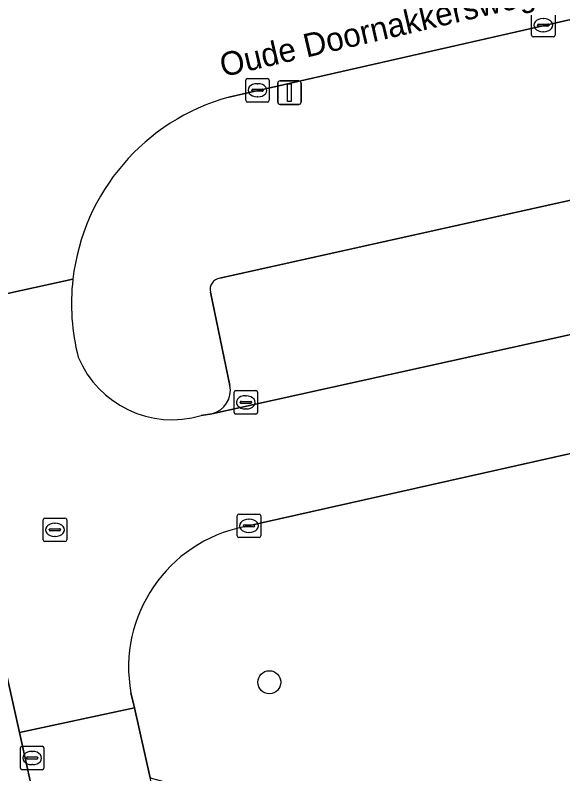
# Model space of a CAD drawing. Extents: x 164494 to 166241, y 382475 to 384495.
# Drawn here: x 164657.42 to 164680.68, y 383414.07 to 383446.31 of the extents above; entities that cross this region are included whole.
import ezdxf

# ---------------------------------------------------------------- set-up
doc = ezdxf.new("R2010")
doc.units = 0
for name, color, linetype in [('IMGEO_Boom', 7, 'Continuous'), ('IMGEO_Erf', 7, 'Continuous'), ('IMGEO_Groenvoorziening', 7, 'Continuous'), ('IMGEO_Kolk', 7, 'Continuous'), ('IMGEO_Lichtmast', 7, 'Continuous'), ('IMGEO_Openbare_ruimte_label', 7, 'Continuous'), ('IMGEO_Parkeervlak_open', 7, 'Continuous'), ('IMGEO_Rijbaan_lokaal_open', 7, 'Continuous'), ('IMGEO_Rioolput', 7, 'Continuous')]:
    doc.layers.add(name, color=color, linetype=linetype)

msp = doc.modelspace()

# ---------------------------------------------------------------- linework, layer by layer
at = {"layer": 'IMGEO_Boom'}
msp.add_circle((164668.213, 383417.967), 0.489, dxfattribs=at)
at = {"layer": 'IMGEO_Erf'}
msp.add_lwpolyline([(164662.088, 383395.82), (164659.432, 383407.619), (164658.436, 383412.043), (164658.352, 383412.424), (164657.598, 383415.827), (164656.836, 383419.271), (164654.781, 383428.342), (164653.876, 383432.334), (164653.262, 383433.646), (164653.108, 383433.931)], dxfattribs=at)
at = {"layer": 'IMGEO_Groenvoorziening'}
for points in [[(164696.172, 383449.592), (164666.487, 383442.83)], [(164666.11, 383435.14), (164701.141, 383442.934)], [(164666.536, 383430.582), (164665.713, 383434.537)], [(164704.167, 383432.878), (164667.135, 383424.569)], [(164665.311, 383429.296), (164665.766, 383429.371)], [(164662.331, 383417.513), (164662.477, 383416.873), (164663.156, 383413.902), (164668.435, 383412.478), (164668.243, 383411.624)]]:
    msp.add_lwpolyline(points, dxfattribs=at)
for centre, radius, start, end in [((164668.92, 383434.047), 9.114, 105.4856, 173.39), ((164668.91, 383434.044), 9.104, 173.3642, 194.4243), ((164666.182, 383434.66), 0.485, 98.564, 194.7162), ((164664.086, 383433.448), 4.329, 202.7182, 286.4403), ((164665.533, 383430.369), 1.025, 283.1335, 11.9669), ((164668.331, 383418.591), 6.097, 101.3178, 190.1851)]:
    msp.add_arc(centre, radius, start, end, dxfattribs=at)
at = {"layer": 'IMGEO_Kolk'}
for p, q in [((164679.349, 383445.461), (164679.349, 383446.313)), ((164680.35, 383446.313), (164680.35, 383445.461)), ((164679.651, 383445.93), (164680.049, 383445.93)), ((164679.837, 383446.167), (164679.862, 383446.167)), ((164679.608, 383445.881), (164679.608, 383445.893)), ((164680.046, 383445.844), (164679.648, 383445.844)), ((164679.86, 383445.607), (164679.835, 383445.607)), ((164680.092, 383445.893), (164680.092, 383445.881)), ((164680.276, 383445.387), (164679.424, 383445.387)), ((164667.207, 383442.695), (164667.207, 383443.547)), ((164667.282, 383443.621), (164668.134, 383443.621)), ((164667.695, 383443.401), (164667.72, 383443.401)), ((164668.208, 383443.547), (164668.208, 383442.695)), ((164667.466, 383443.115), (164667.466, 383443.127)), ((164667.904, 383443.078), (164667.506, 383443.078)), ((164667.509, 383443.164), (164667.907, 383443.164)), ((164667.95, 383443.127), (164667.95, 383443.115)), ((164667.718, 383442.841), (164667.693, 383442.841)), ((164668.134, 383442.621), (164667.282, 383442.621)), ((164666.711, 383429.434), (164666.711, 383430.286)), ((164666.786, 383430.36), (164667.638, 383430.36)), ((164667.199, 383430.14), (164667.224, 383430.14)), ((164667.712, 383430.286), (164667.712, 383429.434)), ((164666.97, 383429.854), (164666.97, 383429.866)), ((164667.408, 383429.817), (164667.01, 383429.817)), ((164667.013, 383429.903), (164667.411, 383429.903)), ((164667.454, 383429.866), (164667.454, 383429.854)), ((164667.222, 383429.58), (164667.197, 383429.58)), ((164667.638, 383429.36), (164666.786, 383429.36)), ((164666.848, 383424.186), (164666.848, 383425.038)), ((164666.923, 383425.112), (164667.775, 383425.112)), ((164667.849, 383425.038), (164667.849, 383424.186)), ((164667.107, 383424.606), (164667.107, 383424.618)), ((164667.15, 383424.655), (164667.548, 383424.655)), ((164667.336, 383424.892), (164667.361, 383424.892)), ((164667.591, 383424.618), (164667.591, 383424.606)), ((164667.545, 383424.569), (164667.147, 383424.569)), ((164667.359, 383424.332), (164667.334, 383424.332)), ((164667.775, 383424.112), (164666.923, 383424.112)), ((164657.637, 383414.32), (164657.637, 383415.172)), ((164657.712, 383415.246), (164658.564, 383415.246)), ((164658.125, 383415.026), (164658.15, 383415.026)), ((164658.638, 383415.172), (164658.638, 383414.32)), ((164657.896, 383414.74), (164657.896, 383414.752)), ((164658.334, 383414.703), (164657.936, 383414.703)), ((164657.939, 383414.789), (164658.337, 383414.789)), ((164658.38, 383414.752), (164658.38, 383414.74)), ((164658.148, 383414.466), (164658.123, 383414.466)), ((164658.564, 383414.246), (164657.712, 383414.246))]:
    msp.add_line(p, q, dxfattribs=at)
for points in [[(164679.349, 383445.461), (164679.349, 383446.313)], [(164680.35, 383446.313), (164680.35, 383445.461)], [(164680.276, 383445.387), (164679.424, 383445.387)], [(164667.207, 383442.695), (164667.207, 383443.547)], [(164667.282, 383443.621), (164668.134, 383443.621)], [(164668.208, 383443.547), (164668.208, 383442.695)], [(164668.134, 383442.621), (164667.282, 383442.621)], [(164666.711, 383429.434), (164666.711, 383430.286)], [(164666.786, 383430.36), (164667.638, 383430.36)], [(164667.712, 383430.286), (164667.712, 383429.434)], [(164667.638, 383429.36), (164666.786, 383429.36)], [(164666.848, 383424.186), (164666.848, 383425.038)], [(164666.923, 383425.112), (164667.775, 383425.112)], [(164667.849, 383425.038), (164667.849, 383424.186)], [(164667.775, 383424.112), (164666.923, 383424.112)], [(164657.637, 383414.32), (164657.637, 383415.172)], [(164657.712, 383415.246), (164658.564, 383415.246)], [(164658.638, 383415.172), (164658.638, 383414.32)], [(164658.564, 383414.246), (164657.712, 383414.246)]]:
    msp.add_lwpolyline(points, dxfattribs=at)
for centre, radius, start, end in [((164679.648, 383445.89), 0.0403, 85.8775, 175.7526), ((164680.053, 383445.892), 0.0386, 1.7309, 96.639), ((164679.645, 383445.88), 0.0366, 178.938, 274.7102), ((164680.049, 383445.887), 0.043, 264.8664, 352.4533), ((164679.426, 383445.463), 0.0765, 181.552, 268.448), ((164679.426, 383445.463), 0.0765, 181.552, 268.448), ((164680.274, 383445.463), 0.0765, 271.552, 358.448), ((164680.274, 383445.463), 0.0765, 271.552, 358.448), ((164667.284, 383443.545), 0.0765, 91.552, 178.448), ((164667.284, 383443.545), 0.0765, 91.552, 178.448), ((164668.132, 383443.545), 0.0765, 1.552, 88.448), ((164668.132, 383443.545), 0.0765, 1.552, 88.448), ((164667.506, 383443.124), 0.0403, 85.8775, 175.7526), ((164667.503, 383443.114), 0.0366, 178.938, 274.7102), ((164667.907, 383443.121), 0.043, 264.8664, 352.4533), ((164667.911, 383443.126), 0.0386, 1.7309, 96.639), ((164667.284, 383442.697), 0.0765, 181.552, 268.448), ((164667.284, 383442.697), 0.0765, 181.552, 268.448), ((164668.132, 383442.697), 0.0765, 271.552, 358.448), ((164668.132, 383442.697), 0.0765, 271.552, 358.448), ((164666.788, 383430.284), 0.0765, 91.552, 178.448), ((164666.788, 383430.284), 0.0765, 91.552, 178.448), ((164667.636, 383430.284), 0.0765, 1.552, 88.448), ((164667.636, 383430.284), 0.0765, 1.552, 88.448), ((164667.01, 383429.863), 0.0403, 85.8775, 175.7526), ((164667.007, 383429.853), 0.0366, 178.938, 274.7102), ((164667.411, 383429.86), 0.043, 264.8664, 352.4533), ((164667.415, 383429.865), 0.0386, 1.7309, 96.639), ((164666.788, 383429.436), 0.0765, 181.552, 268.448), ((164666.788, 383429.436), 0.0765, 181.552, 268.448), ((164667.636, 383429.436), 0.0765, 271.552, 358.448), ((164667.636, 383429.436), 0.0765, 271.552, 358.448), ((164666.925, 383425.036), 0.0765, 91.552, 178.448), ((164666.925, 383425.036), 0.0765, 91.552, 178.448), ((164667.773, 383425.036), 0.0765, 1.552, 88.448), ((164667.773, 383425.036), 0.0765, 1.552, 88.448), ((164667.147, 383424.615), 0.0403, 85.8775, 175.7526), ((164667.552, 383424.617), 0.0386, 1.7309, 96.639), ((164667.144, 383424.605), 0.0366, 178.938, 274.7102), ((164667.548, 383424.612), 0.043, 264.8664, 352.4533), ((164666.925, 383424.188), 0.0765, 181.552, 268.448), ((164666.925, 383424.188), 0.0765, 181.552, 268.448), ((164667.773, 383424.188), 0.0765, 271.552, 358.448), ((164667.773, 383424.188), 0.0765, 271.552, 358.448), ((164657.714, 383415.17), 0.0765, 91.552, 178.448), ((164657.714, 383415.17), 0.0765, 91.552, 178.448), ((164658.562, 383415.17), 0.0765, 1.552, 88.448), ((164658.562, 383415.17), 0.0765, 1.552, 88.448), ((164657.936, 383414.749), 0.0403, 85.8775, 175.7526), ((164657.933, 383414.739), 0.0366, 178.938, 274.7102), ((164658.337, 383414.746), 0.043, 264.8664, 352.4533), ((164658.341, 383414.751), 0.0386, 1.7309, 96.639), ((164657.714, 383414.322), 0.0765, 181.552, 268.448), ((164657.714, 383414.322), 0.0765, 181.552, 268.448), ((164658.562, 383414.322), 0.0765, 271.552, 358.448), ((164658.562, 383414.322), 0.0765, 271.552, 358.448)]:
    msp.add_arc(centre, radius, start, end, dxfattribs=at)
for centre, major_axis, ratio, start_param, end_param in [((164679.836, 383445.887), (-0.387, 0.002), 0.722429, 4.712389, 7.853982), ((164679.861, 383445.887), (-0.39, 0.002), 0.717154, 1.570796, 4.712389), ((164667.694, 383443.121), (-0.387, 0.002), 0.722429, 4.712389, 7.853982), ((164667.719, 383443.121), (-0.39, 0.002), 0.717154, 1.570796, 4.712389), ((164667.198, 383429.86), (-0.387, 0.002), 0.722429, 4.712389, 7.853982), ((164667.223, 383429.86), (-0.39, 0.002), 0.717154, 1.570796, 4.712389), ((164667.335, 383424.612), (-0.387, 0.002), 0.722429, 4.712389, 7.853982), ((164667.36, 383424.612), (-0.39, 0.002), 0.717154, 1.570796, 4.712389), ((164658.124, 383414.746), (-0.387, 0.002), 0.722429, 4.712389, 7.853982), ((164658.149, 383414.746), (-0.39, 0.002), 0.717154, 1.570796, 4.712389)]:
    msp.add_ellipse(centre, major_axis=major_axis, ratio=ratio, start_param=start_param, end_param=end_param, dxfattribs=at)
at = {"layer": 'IMGEO_Lichtmast'}
for p, q in [((164668.568, 383442.621), (164668.568, 383443.421)), ((164668.568, 383443.421), (164668.568, 383442.621)), ((164668.668, 383443.521), (164669.458, 383443.521)), ((164669.458, 383443.521), (164668.668, 383443.521)), ((164669.558, 383443.421), (164669.558, 383442.621)), ((164669.558, 383442.621), (164669.558, 383443.421)), ((164669.458, 383442.521), (164668.668, 383442.521)), ((164668.668, 383442.521), (164669.458, 383442.521))]:
    msp.add_line(p, q, dxfattribs=at)
msp.add_lwpolyline([(164668.988, 383443.396), (164669.138, 383443.396), (164669.138, 383442.646), (164668.988, 383442.646), (164668.988, 383443.396)], dxfattribs=at)
for centre, start, end in [((164668.668, 383443.421), 90, 180), ((164668.668, 383443.421), 90, 180), ((164669.458, 383443.421), 0, 90), ((164669.458, 383443.421), 360, 90), ((164668.668, 383442.621), 180, 270), ((164668.668, 383442.621), 180, 270), ((164669.458, 383442.621), 270, 0), ((164669.458, 383442.621), 270, 0)]:
    msp.add_arc(centre, 0.1, start, end, dxfattribs=at)
at = {"layer": 'IMGEO_Parkeervlak_open'}
for points in [[(164701.141, 383442.934), (164666.11, 383435.14)], [(164665.766, 383429.371), (164703.825, 383437.779)], [(164665.713, 383434.537), (164666.536, 383430.582)]]:
    msp.add_lwpolyline(points, dxfattribs=at)
for centre, radius, start, end in [((164666.182, 383434.66), 0.485, 98.564, 194.7162), ((164665.533, 383430.369), 1.025, 283.1335, 11.9669)]:
    msp.add_arc(centre, radius, start, end, dxfattribs=at)
at = {"layer": 'IMGEO_Rijbaan_lokaal_open'}
for points in [[(164666.487, 383442.83), (164696.172, 383449.592), (164718.625, 383455.027), (164719.856, 383455.391), (164720.68, 383455.635), (164719.895, 383459.238), (164717.739, 383458.983), (164712.427, 383457.585), (164708.916, 383456.753), (164693.004, 383452.936), (164678.342, 383449.582), (164665.421, 383446.666)], [(164650.16, 383445.637), (164653.262, 383433.646), (164659.867, 383435.096)], [(164703.825, 383437.779), (164665.766, 383429.371), (164665.311, 383429.296)], [(164659.867, 383435.096), (164653.262, 383433.646), (164653.876, 383432.334), (164654.781, 383428.342), (164656.836, 383419.271), (164657.598, 383415.827), (164662.477, 383416.873), (164662.331, 383417.513)], [(164667.135, 383424.569), (164704.167, 383432.878)]]:
    msp.add_lwpolyline(points, dxfattribs=at)
msp.add_lwpolyline([(164662.477, 383416.873), (164657.598, 383415.827), (164658.352, 383412.424), (164663.23, 383413.568), (164663.156, 383413.902)], close=True, dxfattribs=at)
for centre, radius, start, end in [((164668.92, 383434.047), 9.114, 105.4856, 173.39), ((164668.91, 383434.044), 9.104, 173.3642, 194.4243), ((164664.086, 383433.448), 4.329, 202.7182, 286.4403), ((164668.331, 383418.591), 6.097, 101.3178, 190.1851)]:
    msp.add_arc(centre, radius, start, end, dxfattribs=at)
at = {"layer": 'IMGEO_Rioolput'}
for p, q in [((164658.679, 383424.944), (164659.531, 383424.944)), ((164658.604, 383424.018), (164658.604, 383424.87)), ((164659.092, 383424.724), (164659.117, 383424.724)), ((164659.605, 383424.87), (164659.605, 383424.018)), ((164658.863, 383424.438), (164658.863, 383424.45)), ((164659.301, 383424.401), (164658.903, 383424.401)), ((164658.906, 383424.487), (164659.304, 383424.487)), ((164659.347, 383424.45), (164659.347, 383424.438)), ((164659.115, 383424.164), (164659.09, 383424.164)), ((164659.531, 383423.944), (164658.679, 383423.944))]:
    msp.add_line(p, q, dxfattribs=at)
for points in [[(164658.679, 383424.944), (164659.531, 383424.944)], [(164658.604, 383424.018), (164658.604, 383424.87)], [(164659.605, 383424.87), (164659.605, 383424.018)], [(164659.531, 383423.944), (164658.679, 383423.944)]]:
    msp.add_lwpolyline(points, dxfattribs=at)
for centre, radius, start, end in [((164658.681, 383424.868), 0.0765, 91.552, 178.448), ((164658.681, 383424.868), 0.0765, 91.552, 178.448), ((164659.529, 383424.868), 0.0765, 1.552, 88.448), ((164659.529, 383424.868), 0.0765, 1.552, 88.448), ((164658.903, 383424.447), 0.0403, 85.8775, 175.7526), ((164658.9, 383424.437), 0.0366, 178.938, 274.7102), ((164659.304, 383424.444), 0.043, 264.8664, 352.4533), ((164659.308, 383424.449), 0.0386, 1.7309, 96.639), ((164658.681, 383424.02), 0.0765, 181.552, 268.448), ((164658.681, 383424.02), 0.0765, 181.552, 268.448), ((164659.529, 383424.02), 0.0765, 271.552, 358.448), ((164659.529, 383424.02), 0.0765, 271.552, 358.448)]:
    msp.add_arc(centre, radius, start, end, dxfattribs=at)
for centre, major_axis, ratio, start_param, end_param in [((164659.091, 383424.444), (-0.387, 0.002), 0.722429, 4.712389, 7.853982), ((164659.116, 383424.444), (-0.39, 0.002), 0.717154, 1.570796, 4.712389)]:
    msp.add_ellipse(centre, major_axis=major_axis, ratio=ratio, start_param=start_param, end_param=end_param, dxfattribs=at)

# ---------------------------------------------------------------- texts
at = {"layer": 'IMGEO_Openbare_ruimte_label'}
msp.add_text('Oude Doornakkersweg', height=1, rotation=13.1191, dxfattribs=at).set_placement((164666.24, 383443.68))

doc.saveas('drawing.dxf')
